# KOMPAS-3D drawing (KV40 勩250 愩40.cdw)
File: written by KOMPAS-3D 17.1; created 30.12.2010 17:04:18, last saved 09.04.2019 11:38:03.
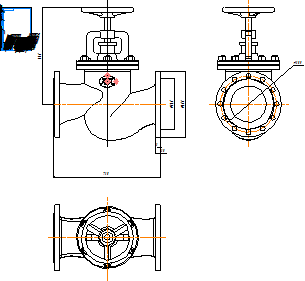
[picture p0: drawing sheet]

Title block, sheet 1: name: KV 40 Ду250; material: Внимание! Данный продукт является объектом авторского права ООО «Торговый Дом АДЛ». / Запрещается изменение, копирование, распространение / (в том числе путем копирования на другие сайты и ресурсы в Интернете) / или любое иное использование информации и объектов без предварительного / согласия правообладателя (ООО «Торговый Дом АДЛ»).; scale: 1:1; sheets: 1; organisation: ООО "Торговый дом АДЛ"; sheet format: A4; stored path: \\adlc.lan\data\АДЛ_ПКД\3D-модели\ADL production\Вентили ГРАНВЕНТ\KV40\KOMPAS 2D\KV 40 Ду250.cdw

Views: Проекционный вид 3, Спереди 1, Проекционный вид 2
Dimensions and other numbers on the sheet: 345; 450; 730; 3; 38; 660; 385; 1:1; 1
